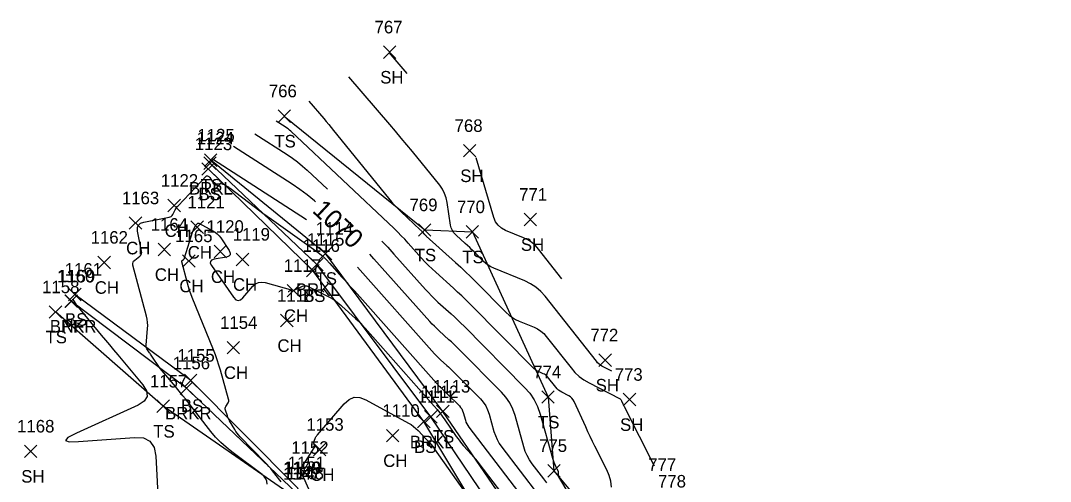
# Model space of a CAD drawing. Extents: x 1592612 to 1596497, y 111838 to 113741.
# Drawn here: x 1592722.3 to 1592886.6, y 113667.2 to 113740.7 of the extents above; entities that cross this region are included whole.
import ezdxf

# ---------------------------------------------------------------- set-up
doc = ezdxf.new("R2010")
doc.units = 0
for name, color, linetype in [('L_A', 7, 'Continuous'), ('L_I', 7, 'Continuous'), ('L_TIC', 7, 'Continuous'), ('LAWE', 7, 'Continuous'), ('LELB', 7, 'Continuous'), ('LSOGCMA', 7, 'Continuous'), ('LSOGCMA_T', 7, 'Continuous'), ('LSOGCMI', 7, 'Continuous')]:
    doc.layers.add(name, color=color, linetype=linetype)

msp = doc.modelspace()

# ---------------------------------------------------------------- linework, layer by layer
at = {"layer": 'L_TIC'}
for points in [[(1592780.17, 113734.66), (1592782.17, 113736.66)], [(1592782.17, 113734.66), (1592780.17, 113736.66)], [(1592763.36, 113724.46), (1592765.36, 113726.46)], [(1592765.36, 113724.46), (1592763.36, 113726.46)], [(1592792.94, 113718.94), (1592794.94, 113720.94)], [(1592794.94, 113718.94), (1592792.94, 113720.94)], [(1592751.51, 113716.95), (1592753.51, 113718.95)], [(1592753.51, 113716.95), (1592751.51, 113718.95)], [(1592751.62, 113717.43), (1592753.62, 113719.43)], [(1592753.62, 113717.43), (1592751.62, 113719.43)], [(1592751.21, 113716.03), (1592753.21, 113718.03)], [(1592753.21, 113716.03), (1592751.21, 113718.03)], [(1592745.79, 113710.2), (1592747.79, 113712.2)], [(1592747.79, 113710.2), (1592745.79, 113712.2)], [(1592739.63, 113707.41), (1592741.63, 113709.41)], [(1592741.63, 113707.41), (1592739.63, 113709.41)], [(1592802.61, 113707.97), (1592804.61, 113709.97)], [(1592804.61, 113707.97), (1592802.61, 113709.97)], [(1592749.47, 113706.74), (1592751.47, 113708.74)], [(1592751.47, 113706.74), (1592749.47, 113708.74)], [(1592785.76, 113706.3), (1592787.76, 113708.3)], [(1592787.76, 113706.3), (1592785.76, 113708.3)], [(1592793.36, 113705.99), (1592795.36, 113707.99)], [(1592795.36, 113705.99), (1592793.36, 113707.99)], [(1592744.21, 113703.18), (1592746.21, 113705.18)], [(1592746.21, 113703.18), (1592744.21, 113705.18)], [(1592753.16, 113702.85), (1592755.16, 113704.85)], [(1592755.16, 113702.85), (1592753.16, 113704.85)], [(1592769.93, 113702.55), (1592771.93, 113704.55)], [(1592771.93, 113702.55), (1592769.93, 113704.55)], [(1592734.63, 113701.12), (1592736.63, 113703.12)], [(1592736.63, 113701.12), (1592734.63, 113703.12)], [(1592748.12, 113701.36), (1592750.12, 113703.36)], [(1592750.12, 113701.36), (1592748.12, 113703.36)], [(1592756.69, 113701.6), (1592758.69, 113703.6)], [(1592758.69, 113701.6), (1592756.69, 113703.6)], [(1592768.55, 113700.79), (1592770.55, 113702.79)], [(1592770.55, 113700.79), (1592768.55, 113702.79)], [(1592767.9, 113699.81), (1592769.9, 113701.81)], [(1592769.9, 113699.81), (1592767.9, 113701.81)], [(1592729.93, 113696.02), (1592731.93, 113698.02)], [(1592731.93, 113696.02), (1592729.93, 113698.02)], [(1592764.82, 113696.62), (1592766.82, 113698.62)], [(1592766.82, 113696.62), (1592764.82, 113698.62)], [(1592729.36, 113694.94), (1592731.36, 113696.94)], [(1592731.36, 113694.94), (1592729.36, 113696.94)], [(1592729.37, 113694.93), (1592731.37, 113696.93)], [(1592731.37, 113694.93), (1592729.37, 113696.93)], [(1592726.85, 113693.22), (1592728.85, 113695.22)], [(1592728.85, 113693.22), (1592726.85, 113695.22)], [(1592763.77, 113691.85), (1592765.77, 113693.85)], [(1592765.77, 113691.85), (1592763.77, 113693.85)], [(1592755.23, 113687.53), (1592757.23, 113689.53)], [(1592757.23, 113687.53), (1592755.23, 113689.53)], [(1592814.55, 113685.54), (1592816.55, 113687.54)], [(1592816.55, 113685.54), (1592814.55, 113687.54)], [(1592748.42, 113682.29), (1592750.42, 113684.29)], [(1592750.42, 113682.29), (1592748.42, 113684.29)], [(1592747.74, 113681.08), (1592749.74, 113683.08)], [(1592749.74, 113681.08), (1592747.74, 113683.08)], [(1592805.43, 113679.65), (1592807.43, 113681.65)], [(1592807.43, 113679.65), (1592805.43, 113681.65)], [(1592818.43, 113679.25), (1592820.43, 113681.25)], [(1592820.43, 113679.25), (1592818.43, 113681.25)], [(1592744.04, 113678.18), (1592746.04, 113680.18)], [(1592746.04, 113678.18), (1592744.04, 113680.18)], [(1592788.64, 113677.37), (1592790.64, 113679.37)], [(1592790.64, 113677.37), (1592788.64, 113679.37)], [(1592785.61, 113675.74), (1592787.61, 113677.74)], [(1592787.61, 113675.74), (1592785.61, 113677.74)], [(1592786.75, 113676.48), (1592788.75, 113678.48)], [(1592788.75, 113676.48), (1592786.75, 113678.48)], [(1592780.65, 113673.5), (1592782.65, 113675.5)], [(1592782.65, 113673.5), (1592780.65, 113675.5)], [(1592722.9, 113671), (1592724.9, 113673)], [(1592724.9, 113671), (1592722.9, 113673)], [(1592769.01, 113671.28), (1592771.01, 113673.28)], [(1592771.01, 113671.28), (1592769.01, 113673.28)], [(1592766.59, 113667.6), (1592768.59, 113669.6)], [(1592768.59, 113667.6), (1592766.59, 113669.6)], [(1592806.38, 113667.89), (1592808.38, 113669.89)], [(1592808.38, 113667.89), (1592806.38, 113669.89)]]:
    msp.add_lwpolyline(points, dxfattribs=at)
at = {"layer": 'LAWE'}
for points in [[(1592886.54, 113460.92), (1592877.74, 113481.57), (1592863.09, 113501.14), (1592852.9, 113518.21), (1592848.8, 113541.38), (1592835.88, 113571.62), (1592826.21, 113590), (1592821.08, 113603.1), (1592811.5, 113625.05), (1592801.91, 113656.5), (1592787.75, 113677.48), (1592769.55, 113701.79), (1592752.51, 113717.95)], [(1592867.65, 113460.38), (1592859.41, 113477.51), (1592844.79, 113495.55), (1592832.37, 113516.6), (1592826.93, 113530.55), (1592818.76, 113547.94), (1592807.6, 113581.11), (1592797.67, 113603.18), (1592787.51, 113626.88), (1592776.48, 113646.36), (1592766.38, 113665.34), (1592748.74, 113682.08), (1592730.36, 113695.94)]]:
    msp.add_lwpolyline(points, dxfattribs=at)
at = {"layer": 'LELB'}
for points in [[(1592764.36, 113725.46), (1592786.76, 113707.3), (1592794.36, 113706.99), (1592806.43, 113680.65), (1592807.38, 113668.89), (1592816.06, 113658.43), (1592824.78, 113665.88), (1592828.39, 113642.22), (1592829.2, 113619.13), (1592847.35, 113605.45), (1592857.77, 113601.14), (1592858.44, 113592.42), (1592865.76, 113577.69)], [(1592886.58, 113460.95), (1592879.78, 113482.31), (1592863.97, 113501.75), (1592853.37, 113518.29), (1592851.19, 113542.04), (1592841.02, 113567.09), (1592831.52, 113591.89), (1592821.82, 113602.81), (1592813.33, 113624.79), (1592804.23, 113657.07), (1592789.64, 113678.37), (1592770.93, 113703.55), (1592752.62, 113718.43)], [(1592886.43, 113460.85), (1592879.54, 113465.93), (1592876.14, 113481.19), (1592862.3, 113500.64), (1592852.53, 113517.93), (1592848.16, 113540.89), (1592835.18, 113571.26), (1592825.2, 113589.93), (1592820.42, 113603.3), (1592810.03, 113625.39), (1592799.47, 113655.33), (1592786.61, 113676.74), (1592768.9, 113700.81), (1592752.21, 113717.03)], [(1592869.1, 113460.4), (1592860.44, 113478.12), (1592844.63, 113496.56), (1592834.16, 113516.96), (1592828.4, 113531.17), (1592823.56, 113549.92), (1592808.46, 113581.72), (1592799.53, 113603.06), (1592789.48, 113627.85), (1592777.21, 113647.43), (1592766.46, 113666.15), (1592749.42, 113683.29), (1592730.93, 113697.02)], [(1592856.49, 113476.87), (1592843.19, 113495.05), (1592831.69, 113516.66), (1592823.2, 113528.69), (1592814.85, 113545.46), (1592806.8, 113580.85), (1592796.45, 113601.85), (1592785.29, 113626.35), (1592775.72, 113645.65), (1592766.31, 113664.45), (1592745.04, 113679.18), (1592727.85, 113694.22)]]:
    msp.add_lwpolyline(points, dxfattribs=at)
at = {"layer": 'LSOGCMA'}
for points in [[(1592783.94, 113732.26), (1592781.07, 113735.6)], [(1592769.36, 113711.78), (1592769.15, 113711.96), (1592768.01, 113712.89), (1592766.84, 113713.77), (1592765.62, 113714.6), (1592756.27, 113720.61)], [(1592808.64, 113699.52), (1592804.92, 113704.25), (1592804.41, 113704.82), (1592803.84, 113705.31), (1592803.21, 113705.72), (1592802.53, 113706.05), (1592799.65, 113707.23), (1592799, 113707.58), (1592798.46, 113708.04), (1592798.06, 113708.62), (1592797.77, 113709.3), (1592794.95, 113718.8)], [(1592806.23, 113666.97), (1592805.77, 113667.59), (1592803.91, 113670.02), (1592803.48, 113670.65), (1592803.11, 113671.31), (1592802.81, 113671.99), (1592802.57, 113672.72), (1592801.17, 113677.7), (1592800.81, 113678.74), (1592800.33, 113679.71), (1592799.72, 113680.62), (1592798.99, 113681.45), (1592792.15, 113688.36), (1592791.78, 113688.73), (1592791.4, 113689.09), (1592791.02, 113689.45), (1592790.63, 113689.8), (1592789.07, 113691.21), (1592788.69, 113691.56), (1592788.31, 113691.93), (1592787.95, 113692.3), (1592787.59, 113692.69), (1592778.65, 113702.71), (1592777.99, 113703.44)]]:
    msp.add_lwpolyline(points, dxfattribs=at)
at = {"layer": 'LSOGCMI'}
for points in [[(1592816.63, 113684.78), (1592815.04, 113685.6), (1592814.79, 113685.75), (1592814.55, 113685.93), (1592814.34, 113686.12), (1592814.15, 113686.35), (1592805.98, 113696.72), (1592805.28, 113697.5), (1592804.51, 113698.17), (1592803.65, 113698.73), (1592802.71, 113699.18), (1592797.78, 113701.2), (1592797.32, 113701.42), (1592796.89, 113701.67), (1592796.49, 113701.97), (1592796.11, 113702.32), (1592794.64, 113703.81), (1592794.29, 113704.15), (1592793.94, 113704.49), (1592793.58, 113704.83), (1592793.22, 113705.16), (1592791.76, 113706.47), (1592791.43, 113706.82), (1592791.18, 113707.2), (1592791, 113707.63), (1592790.89, 113708.09), (1592790.35, 113711.7), (1592790.19, 113712.44), (1592789.94, 113713.14), (1592789.59, 113713.8), (1592789.15, 113714.42), (1592784.8, 113719.79), (1592783.91, 113720.88), (1592783.01, 113721.96), (1592782.11, 113723.04), (1592781.19, 113724.11), (1592774.67, 113731.72)], [(1592768.27, 113727.84), (1592770.65, 113725.06), (1592771.05, 113724.6), (1592771.44, 113724.13), (1592771.83, 113723.66), (1592772.22, 113723.19), (1592780.98, 113712.37), (1592781.46, 113711.81), (1592781.95, 113711.26), (1592782.46, 113710.73), (1592782.99, 113710.21), (1592786.05, 113707.33), (1592786.13, 113707.25), (1592786.22, 113707.17), (1592786.3, 113707.08), (1592786.37, 113707), (1592786.68, 113706.65), (1592786.76, 113706.57), (1592786.84, 113706.48), (1592786.93, 113706.4), (1592787.01, 113706.32), (1592791.69, 113702.11), (1592792.5, 113701.37), (1592793.29, 113700.63), (1592794.07, 113699.87), (1592794.85, 113699.1), (1592799.77, 113694.13), (1592800.24, 113693.7), (1592800.74, 113693.33), (1592801.27, 113693.01), (1592801.84, 113692.75), (1592804.2, 113691.78), (1592804.76, 113691.51), (1592805.27, 113691.17), (1592805.74, 113690.77), (1592806.16, 113690.3), (1592810.11, 113685.29), (1592810.73, 113684.58), (1592811.42, 113683.95), (1592812.17, 113683.39), (1592812.98, 113682.92), (1592817.84, 113680.41), (1592817.94, 113680.34), (1592818.03, 113680.26), (1592818.11, 113680.17), (1592818.17, 113680.06), (1592818.38, 113679.59), (1592818.44, 113679.48), (1592818.49, 113679.36), (1592818.55, 113679.25), (1592818.6, 113679.13), (1592823.36, 113669.69)], [(1592816.58, 113666.28), (1592816.45, 113667.23), (1592816.2, 113668.15), (1592815.82, 113669.04), (1592813.92, 113672.81), (1592813.54, 113673.57), (1592813.17, 113674.34), (1592812.8, 113675.11), (1592812.44, 113675.88), (1592810.59, 113679.95), (1592810.44, 113680.22), (1592810.25, 113680.46), (1592810.03, 113680.66), (1592809.76, 113680.83), (1592808.63, 113681.41), (1592808.35, 113681.57), (1592808.1, 113681.76), (1592807.87, 113681.97), (1592807.66, 113682.21), (1592806.34, 113683.89), (1592806.2, 113684.04), (1592806.04, 113684.18), (1592805.87, 113684.29), (1592805.68, 113684.38), (1592804.9, 113684.7), (1592804.7, 113684.79), (1592804.53, 113684.9), (1592804.36, 113685.03), (1592804.2, 113685.17), (1592793.95, 113695.52), (1592793.31, 113696.16), (1592792.66, 113696.78), (1592792.01, 113697.4), (1592791.34, 113698.01), (1592788.52, 113700.55), (1592787.93, 113701.09), (1592787.35, 113701.65), (1592786.8, 113702.23), (1592786.25, 113702.82), (1592784.11, 113705.22), (1592783.57, 113705.81), (1592783.02, 113706.39), (1592782.45, 113706.96), (1592781.87, 113707.52), (1592765.38, 113723.05), (1592765.17, 113723.24), (1592764.95, 113723.42), (1592764.72, 113723.59), (1592764.48, 113723.75), (1592763.04, 113724.67)], [(1592759.66, 113722.64), (1592764.81, 113719.33), (1592765.66, 113718.75), (1592766.47, 113718.15), (1592767.26, 113717.5), (1592768.02, 113716.82), (1592771.24, 113713.79)], [(1592767.88, 113708.93), (1592752.88, 113718.58)], [(1592761.65, 113666.75), (1592761.58, 113667.21), (1592761.42, 113667.62), (1592761.17, 113667.98), (1592760.82, 113668.29), (1592755.97, 113671.91), (1592755.06, 113672.64), (1592754.21, 113673.42), (1592753.4, 113674.26), (1592752.65, 113675.15), (1592748.57, 113680.35), (1592748.18, 113680.85), (1592747.79, 113681.34), (1592747.39, 113681.83), (1592746.99, 113682.31), (1592744.57, 113685.22), (1592744.57, 113685.23), (1592743.11, 113687.35), (1592743.02, 113687.47), (1592742.94, 113687.6), (1592742.85, 113687.72), (1592742.77, 113687.85), (1592742.44, 113688.35), (1592742.37, 113688.47), (1592742.32, 113688.61), (1592742.3, 113688.75), (1592742.3, 113688.9), (1592742.54, 113691.57), (1592742.56, 113692.07), (1592742.54, 113692.56), (1592742.48, 113693.05), (1592742.37, 113693.53), (1592740.21, 113701.71), (1592740.18, 113701.95), (1592740.22, 113702.16), (1592740.32, 113702.34), (1592740.49, 113702.51), (1592741.29, 113703.12), (1592741.46, 113703.29), (1592741.57, 113703.47), (1592741.61, 113703.69), (1592741.59, 113703.92), (1592740.94, 113707.11), (1592740.91, 113707.67), (1592741.07, 113708.09), (1592741.4, 113708.39), (1592741.93, 113708.57), (1592745.98, 113709.32), (1592746.17, 113709.38), (1592746.33, 113709.47), (1592746.46, 113709.6), (1592746.57, 113709.77), (1592746.95, 113710.5), (1592747.05, 113710.68), (1592747.16, 113710.86), (1592747.28, 113711.02), (1592747.42, 113711.17), (1592751.94, 113715.91), (1592751.98, 113715.94), (1592752.02, 113715.95), (1592752.07, 113715.95), (1592752.11, 113715.93), (1592752.3, 113715.83), (1592752.35, 113715.8), (1592752.39, 113715.77), (1592752.42, 113715.73), (1592752.46, 113715.69), (1592752.91, 113715), (1592753, 113714.89), (1592753.12, 113714.8), (1592753.25, 113714.74), (1592753.39, 113714.72), (1592754.43, 113714.65), (1592754.55, 113714.63), (1592754.67, 113714.6), (1592754.78, 113714.56), (1592754.89, 113714.5), (1592755.32, 113714.24), (1592755.43, 113714.17), (1592755.53, 113714.1), (1592755.63, 113714.03), (1592755.73, 113713.96), (1592759.56, 113711.02), (1592760.24, 113710.51), (1592760.91, 113710), (1592761.6, 113709.5), (1592762.29, 113709.01), (1592769.38, 113703.98), (1592769.98, 113703.53), (1592770.54, 113703.06), (1592771.08, 113702.55), (1592771.58, 113702.01), (1592773.56, 113699.79), (1592774.06, 113699.24), (1592774.55, 113698.68), (1592775.05, 113698.13), (1592775.54, 113697.57), (1592789.07, 113682.41), (1592789.17, 113682.31), (1592789.27, 113682.2), (1592789.37, 113682.1), (1592789.48, 113681.99), (1592789.92, 113681.6), (1592790.03, 113681.5), (1592790.14, 113681.4), (1592790.25, 113681.29), (1592790.35, 113681.19), (1592792.29, 113679.24), (1592792.49, 113679), (1592792.66, 113678.75), (1592792.8, 113678.47), (1592792.9, 113678.18), (1592793.24, 113676.96), (1592793.34, 113676.67), (1592793.47, 113676.38), (1592793.62, 113676.11), (1592793.8, 113675.85), (1592804.63, 113661.67)], [(1592763.85, 113667.14), (1592763.62, 113667.41), (1592762.46, 113668.89), (1592762.19, 113669.23), (1592761.91, 113669.55), (1592761.62, 113669.88), (1592761.32, 113670.19), (1592757.26, 113674.35), (1592757.03, 113674.61), (1592756.82, 113674.87), (1592756.62, 113675.15), (1592756.45, 113675.45), (1592755.64, 113676.87), (1592755.54, 113677.06), (1592755.45, 113677.25), (1592755.37, 113677.45), (1592755.29, 113677.65), (1592754.98, 113678.57), (1592754.94, 113678.73), (1592754.94, 113678.88), (1592754.98, 113679.02), (1592755.05, 113679.16), (1592755.4, 113679.72), (1592755.47, 113679.86), (1592755.51, 113680.01), (1592755.51, 113680.16), (1592755.48, 113680.31), (1592754.17, 113684.94), (1592753.92, 113685.76), (1592753.66, 113686.57), (1592753.37, 113687.37), (1592753.05, 113688.17), (1592749.65, 113696.52), (1592749.43, 113697.09), (1592749.23, 113697.66), (1592749.05, 113698.24), (1592748.89, 113698.82), (1592747.99, 113702.2), (1592747.99, 113702.27), (1592748, 113702.33), (1592748.02, 113702.38), (1592748.07, 113702.43), (1592748.3, 113702.6), (1592748.35, 113702.65), (1592748.4, 113702.7), (1592748.43, 113702.76), (1592748.46, 113702.83), (1592749.78, 113707.13), (1592749.81, 113707.22), (1592749.85, 113707.31), (1592749.89, 113707.4), (1592749.93, 113707.49), (1592750.12, 113707.87), (1592750.16, 113707.93), (1592750.2, 113707.99), (1592750.24, 113708.05), (1592750.29, 113708.11), (1592750.49, 113708.32), (1592750.55, 113708.36), (1592750.6, 113708.38), (1592750.66, 113708.38), (1592750.73, 113708.36), (1592752.95, 113707.18), (1592753.32, 113706.95), (1592753.66, 113706.68), (1592753.96, 113706.37), (1592754.22, 113706.02), (1592755.54, 113704), (1592755.72, 113703.62), (1592755.71, 113703.33), (1592755.5, 113703.11), (1592755.11, 113702.98), (1592753.15, 113702.62), (1592752.76, 113702.49), (1592752.56, 113702.28), (1592752.55, 113702), (1592752.74, 113701.63), (1592756.27, 113696.56), (1592756.62, 113696.18), (1592756.98, 113696.04), (1592757.36, 113696.14), (1592757.75, 113696.48), (1592759.34, 113698.31), (1592759.76, 113698.69), (1592760.23, 113698.92), (1592760.74, 113698.99), (1592761.3, 113698.91), (1592765.66, 113697.7), (1592765.68, 113697.7), (1592765.7, 113697.69), (1592765.72, 113697.69), (1592765.74, 113697.69), (1592765.83, 113697.68), (1592765.85, 113697.68), (1592765.87, 113697.69), (1592765.89, 113697.69), (1592765.91, 113697.7), (1592767.25, 113698.31), (1592767.48, 113698.39), (1592767.71, 113698.41), (1592767.94, 113698.38), (1592768.16, 113698.29), (1592771.98, 113696.36), (1592772.13, 113696.28), (1592772.27, 113696.2), (1592772.4, 113696.1), (1592772.54, 113696), (1592773.05, 113695.57), (1592773.18, 113695.46), (1592773.3, 113695.35), (1592773.43, 113695.24), (1592773.55, 113695.13), (1592775.74, 113693.17), (1592776.14, 113692.8), (1592776.52, 113692.42), (1592776.9, 113692.03), (1592777.27, 113691.63), (1592788.27, 113679.19), (1592788.72, 113678.67), (1592789.15, 113678.13), (1592789.57, 113677.58), (1592789.97, 113677.01), (1592791.8, 113674.35), (1592792.07, 113673.97), (1592792.36, 113673.6), (1592792.65, 113673.23), (1592792.96, 113672.88), (1592794.21, 113671.48), (1592794.52, 113671.13), (1592794.82, 113670.77), (1592795.12, 113670.41), (1592795.41, 113670.04), (1592804.34, 113658.35)], [(1592779.93, 113705.51), (1592780.85, 113704.54), (1592781.85, 113703.44), (1592786.86, 113697.83), (1592787.34, 113697.3), (1592787.84, 113696.79), (1592788.34, 113696.3), (1592788.87, 113695.81), (1592790.99, 113693.9), (1592791.51, 113693.42), (1592792.03, 113692.94), (1592792.54, 113692.44), (1592793.05, 113691.94), (1592802.69, 113682.2), (1592803.52, 113681.26), (1592804.21, 113680.23), (1592804.76, 113679.12), (1592805.18, 113677.93), (1592807.15, 113670.89), (1592807.2, 113670.73), (1592807.25, 113670.56), (1592807.32, 113670.4), (1592807.38, 113670.24), (1592807.75, 113669.44), (1592807.78, 113669.37), (1592807.81, 113669.31), (1592807.85, 113669.24), (1592807.88, 113669.17), (1592808.01, 113668.9), (1592808.04, 113668.84), (1592808.06, 113668.77), (1592808.07, 113668.7), (1592808.07, 113668.62), (1592808.05, 113668.26), (1592808.05, 113668.18), (1592808.07, 113668.1), (1592808.09, 113668.02), (1592808.13, 113667.95), (1592813.67, 113658.55)], [(1592776.02, 113701.35), (1592788.33, 113687.55), (1592788.56, 113687.3), (1592788.79, 113687.06), (1592789.03, 113686.83), (1592789.28, 113686.6), (1592790.28, 113685.7), (1592790.53, 113685.47), (1592790.77, 113685.24), (1592791.01, 113685.01), (1592791.25, 113684.77), (1592795.64, 113680.34), (1592796.11, 113679.81), (1592796.49, 113679.23), (1592796.8, 113678.61), (1592797.04, 113677.94), (1592797.81, 113675.18), (1592798.03, 113674.5), (1592798.32, 113673.86), (1592798.66, 113673.24), (1592799.07, 113672.66), (1592804.93, 113664.99)], [(1592730.55, 113696.31), (1592731.1, 113695.47), (1592731.11, 113695.45), (1592731.13, 113695.43), (1592731.14, 113695.41), (1592731.15, 113695.4), (1592731.22, 113695.29), (1592731.23, 113695.28), (1592731.23, 113695.27), (1592731.24, 113695.27), (1592735.16, 113690.54), (1592735.82, 113689.75), (1592736.47, 113688.97), (1592737.13, 113688.18), (1592737.78, 113687.39), (1592741.77, 113682.62), (1592742.39, 113681.62), (1592742.47, 113680.75), (1592742.01, 113679.99), (1592741.03, 113679.36), (1592731.19, 113674.9), (1592729.83, 113674.19), (1592729.43, 113673.72), (1592730.01, 113673.51), (1592731.54, 113673.54), (1592740.45, 113674.22), (1592741.87, 113674.13), (1592742.91, 113673.6), (1592743.57, 113672.63), (1592743.85, 113671.23), (1592744.27, 113663.07)], [(1592768.87, 113664.62), (1592767.45, 113667.77), (1592767.39, 113667.9), (1592767.34, 113668.04), (1592767.29, 113668.17), (1592767.24, 113668.3), (1592767.05, 113668.84), (1592767.02, 113668.97), (1592767.02, 113669.1), (1592767.05, 113669.23), (1592767.11, 113669.35), (1592769.12, 113672.53), (1592769.17, 113672.61), (1592769.19, 113672.7), (1592769.19, 113672.79), (1592769.17, 113672.89), (1592769.07, 113673.27), (1592769.05, 113673.36), (1592769.05, 113673.46), (1592769.06, 113673.55), (1592769.1, 113673.64), (1592769.35, 113674.18), (1592769.41, 113674.3), (1592769.48, 113674.41), (1592769.56, 113674.52), (1592769.64, 113674.62), (1592773.91, 113679.59), (1592774.68, 113680.27), (1592775.51, 113680.61), (1592776.41, 113680.59), (1592777.38, 113680.22), (1592784.16, 113676.5), (1592784.58, 113676.25), (1592784.98, 113675.97), (1592785.36, 113675.65), (1592785.71, 113675.31), (1592787.07, 113673.87), (1592787.41, 113673.51), (1592787.73, 113673.13), (1592788.03, 113672.74), (1592788.32, 113672.34), (1592793.94, 113664.38)]]:
    msp.add_lwpolyline(points, dxfattribs=at)

# ---------------------------------------------------------------- texts
at = {"layer": 'L_A'}
for s, p in [('SH', (1592779.66, 113730.66)), ('TS', (1592762.77, 113720.46)), ('TS', (1592751.03, 113713.43)), ('SH', (1592792.43, 113714.94)), ('BRKL', (1592749.15, 113712.95)), ('BS', (1592750.65, 113712.03)), ('CH', (1592745.27, 113706.2)), ('SH', (1592802.1, 113703.97)), ('CH', (1592739.12, 113703.41)), ('CH', (1592748.95, 113702.74)), ('TS', (1592785.17, 113702.3)), ('TS', (1592792.77, 113701.99)), ('CH', (1592743.7, 113699.18)), ('CH', (1592752.65, 113698.85)), ('CH', (1592734.12, 113697.12)), ('CH', (1592747.61, 113697.36)), ('CH', (1592756.17, 113697.6)), ('TS', (1592769.34, 113698.55)), ('BRKL', (1592766.2, 113696.79)), ('BS', (1592767.34, 113695.81)), ('CH', (1592764.3, 113692.62)), ('BRKR', (1592726.95, 113690.94)), ('NF', (1592728.85, 113690.93)), ('BS', (1592729.37, 113692.02)), ('TS', (1592726.26, 113689.22)), ('CH', (1592763.26, 113687.85)), ('CH', (1592754.72, 113683.53)), ('SH', (1592814.04, 113681.54)), ('BS', (1592747.86, 113678.29)), ('BRKR', (1592745.33, 113677.08)), ('TS', (1592804.84, 113675.65)), ('TS', (1592743.45, 113674.18)), ('SH', (1592817.92, 113675.25)), ('BRKL', (1592784.39, 113672.48)), ('TS', (1592788.05, 113673.37)), ('BS', (1592785.05, 113671.74)), ('CH', (1592780.14, 113669.5)), ('SH', (1592722.39, 113667)), ('CH', (1592768.5, 113667.28))]:
    msp.add_text(s, height=2, dxfattribs=at).set_placement(p)
at = {"layer": 'L_I'}
for s, p in [('767', (1592778.76, 113738.66)), ('766', (1592761.89, 113728.46)), ('768', (1592791.53, 113722.94)), ('1123', (1592750.09, 113720.03)), ('1124', (1592750.38, 113720.95)), ('1125', (1592750.5, 113721.43)), ('1122', (1592744.66, 113714.2)), ('771', (1592801.82, 113711.97)), ('1163', (1592738.45, 113711.41)), ('1121', (1592748.91, 113710.74)), ('769', (1592784.34, 113710.3)), ('770', (1592791.91, 113709.99)), ('1164', (1592743.04, 113707.18)), ('1120', (1592751.95, 113706.85)), ('1165', (1592746.95, 113705.36)), ('1119', (1592756.12, 113705.6)), ('1114', (1592769.38, 113706.55)), ('1162', (1592733.46, 113705.12)), ('1116', (1592767.28, 113703.81)), ('1115', (1592767.99, 113704.79)), ('1117', (1592764.26, 113700.62)), ('1160', (1592728.1, 113698.94)), ('1159', (1592728.23, 113698.93)), ('1161', (1592729.33, 113700.02)), ('1158', (1592725.72, 113697.22)), ('1118', (1592763.21, 113695.85)), ('1154', (1592754.11, 113691.53)), ('772', (1592813.18, 113689.54)), ('1155', (1592747.3, 113686.29)), ('1156', (1592746.56, 113685.08)), ('774', (1592804.07, 113683.65)), ('773', (1592817.07, 113683.25)), ('1157', (1592742.92, 113682.18)), ('1113', (1592788.08, 113681.37)), ('1111', (1592785.62, 113679.74)), ('1112', (1592786.19, 113680.48)), ('1110', (1592780.01, 113677.5)), ('1168', (1592721.73, 113675)), ('1153', (1592767.89, 113675.28)), ('1152', (1592765.47, 113671.6)), ('775', (1592805.01, 113671.89)), ('1151', (1592764.9, 113669.15)), ('1150', (1592764.17, 113668.34)), ('1147', (1592764.18, 113667.45)), ('1149', (1592764.34, 113668.36)), ('1148', (1592764.72, 113667.52)), ('777', (1592822.42, 113668.88)), ('778', (1592823.98, 113666.22))]:
    msp.add_text(s, height=2, dxfattribs=at).set_placement(p)
at = {"layer": 'LSOGCMA_T'}
msp.add_text('1070', height=3, rotation=316.8674, dxfattribs=at).set_placement((1592768.68, 113710.23))

doc.saveas('drawing.dxf')
